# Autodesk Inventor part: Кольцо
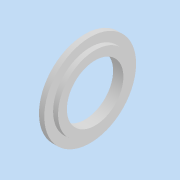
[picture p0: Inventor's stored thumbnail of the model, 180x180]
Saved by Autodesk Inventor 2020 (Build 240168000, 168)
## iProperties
Created: 2024-03
Part Number: Кольцо
Material: Типовые
Document SubType Name: Modeling
Designer: User
Density: 1 g/cm^3
Appearance: По умолчанию
Author: User
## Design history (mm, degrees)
sketch "Эскиз1"
  geometry: C1 r 26 at (0, 0); 1 further point
  constraints: 1 centre point, 1 coincident
  dimensions: "d0" = 52 diameter of C1
extrude "Выдавливание1" new body sketch "Эскиз1" distance "d1" = 3; taper "d2" = 0 deg
sketch "Эскиз2"
  geometry: C1 r 21 at (0, 0); 1 further point
  constraints: 1 centre point, 1 coincident
  dimensions: "d3" = 42 diameter of C1
extrude "Выдавливание2" join sketch "Эскиз2" distance "d4" = 2.8; taper "d5" = 0 deg
sketch "Эскиз3"
  geometry: C1 r 16 at (0, 0); 1 further point
  constraints: 1 centre point, 1 coincident
  dimensions: "d6" = 32 diameter of C1
extrude "Выдавливание3" cut sketch "Эскиз3" distance "d7" = 100; taper "d8" = 0 deg
node "Твердое тело1"
